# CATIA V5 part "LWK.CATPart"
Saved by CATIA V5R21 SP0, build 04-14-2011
Part number: LWK.SLDPRT
Bounding box of the stored display mesh (mm): x -1.362 to 1.338, y -0.976 to 1.024, z 2.1 to 2.7
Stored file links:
  C:\Users\user\Desktop\CATIA文件\0-最新文件\LWK\LWK.CATPart
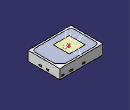
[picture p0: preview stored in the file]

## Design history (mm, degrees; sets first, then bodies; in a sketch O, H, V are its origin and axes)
AxisSystem1: origin (-0.0115, 0.0244, 2.7), X (0, 1, 0), Y (-1, 0, 0), Z (0, 0, 1)
Set1
  DatumSurface1 to DatumSurface42
  Line1: stored without definition
  Circle1: stored without definition
  Line2: stored without definition
  Circle2: stored without definition
  Line3: stored without definition
  Circle3: stored without definition
  Line4: stored without definition
  Circle4: stored without definition
  Line5: stored without definition
  Circle5: stored without definition
  Line6: stored without definition
  Circle6: stored without definition
  Line7: stored without definition
  Circle7: stored without definition
  Line8: stored without definition
  Line9: stored without definition
  Circle8: stored without definition
  Line10: stored without definition
  Line11: stored without definition
  Circle9: stored without definition
  Line12: stored without definition
  Line13: stored without definition
  Circle10: stored without definition
  Line14 to Line18: stored without definition
  Circle11: stored without definition
  Line19: stored without definition
  Circle12: stored without definition
  Line20: stored without definition
  Circle13: stored without definition
  Line21: stored without definition
  Circle14: stored without definition
  Line22: stored without definition
  Circle15: stored without definition
  Line23: stored without definition
  Circle16: stored without definition
  Line24: stored without definition
  Circle17: stored without definition
  Line25: stored without definition
  Circle18: stored without definition
  Line26: stored without definition
  Circle19: stored without definition
  Line27: stored without definition
  Circle20: stored without definition
  Line28 to Line30: stored without definition
  Circle21: stored without definition
  Line31: stored without definition
  Circle22: stored without definition
  Line32: stored without definition
  Circle23: stored without definition
  Line33: stored without definition
  Circle24: stored without definition
  Line34: stored without definition
  Line35: stored without definition
  Circle25: stored without definition
  Line36: stored without definition
  Circle26: stored without definition
  Line37: stored without definition
  Circle27: stored without definition
  Line38: stored without definition
  Circle28: stored without definition
  Line39: stored without definition
  Circle29: stored without definition
  Line40: stored without definition
  Circle30: stored without definition
  Line41: stored without definition
  Circle31: stored without definition
  Line42: stored without definition
  Circle32: stored without definition
  Line43: stored without definition
  Circle33: stored without definition
  Line44 to Line46: stored without definition
  Circle34: stored without definition
  Line47: stored without definition
  Circle35: stored without definition
  Line48: stored without definition
  Circle36: stored without definition
  Line49: stored without definition
  Circle37: stored without definition
  Line50: stored without definition
  Circle38: stored without definition
  Line51 to Line79: stored without definition
  DatumSurface43 to DatumSurface79
  Line80: stored without definition
  Circle39: stored without definition
  Line81: stored without definition
  Circle40: stored without definition
  Line82: stored without definition
  Circle41: stored without definition
  Line83: stored without definition
  Circle42: stored without definition
  Circle43: stored without definition
  Line84 to Line87: stored without definition
  Circle44: stored without definition
  Line88 to Line90: stored without definition
  Circle45: stored without definition
  Line91 to Line93: stored without definition
  Circle46: stored without definition
  Line94: stored without definition
  Line95: stored without definition
  Circle47: stored without definition
  Line96: stored without definition
  Circle48: stored without definition
  Line97: stored without definition
  Circle49: stored without definition
  Line98 to Line100: stored without definition
  Circle50: stored without definition
  Line101: stored without definition
  Circle51: stored without definition
  Line102: stored without definition
  Circle52: stored without definition
  Line103: stored without definition
  Circle53: stored without definition
  Line104: stored without definition
  Circle54: stored without definition
  Line105 to Line107: stored without definition
  Circle55: stored without definition
  Line108: stored without definition
  Circle56: stored without definition
  Line109 to Line112: stored without definition
  Circle57: stored without definition
  Line113: stored without definition
  Circle58: stored without definition
  Line114: stored without definition
  Circle59: stored without definition
  Line115 to Line117: stored without definition
  Circle60: stored without definition
  Line118: stored without definition
  Circle61: stored without definition
  Line119: stored without definition
  Circle62: stored without definition
  Line120: stored without definition
  Circle63: stored without definition
  Line121: stored without definition
  Circle64: stored without definition
  Line122 to Line124: stored without definition
  Circle65: stored without definition
  Line125: stored without definition
  Circle66: stored without definition
  Line126 to Line153: stored without definition
  DatumSurface80 to DatumSurface154
  DatumCurve1
  DatumCurve2
  Circle67: stored without definition
  Line154: stored without definition
  Circle68: stored without definition
  Line155: stored without definition
  Line156: stored without definition
  Circle69: stored without definition
  Line157: stored without definition
  Circle70: stored without definition
  Line158 to Line160: stored without definition
  Circle71: stored without definition
  Line161: stored without definition
  Circle72: stored without definition
  Line162 to Line164: stored without definition
  Circle73: stored without definition
  Line165: stored without definition
  Circle74: stored without definition
  Line166 to Line168: stored without definition
  Circle75: stored without definition
  Line169: stored without definition
  Circle76: stored without definition
  Line170: stored without definition
  Line171: stored without definition
  Circle77: stored without definition
  Line172: stored without definition
  Circle78: stored without definition
  Line173: stored without definition
  Circle79: stored without definition
  Line174 to Line176: stored without definition
  Circle80: stored without definition
  Line177: stored without definition
  Circle81: stored without definition
  Line178: stored without definition
  Circle82: stored without definition
  Line179: stored without definition
  Circle83: stored without definition
  Line180: stored without definition
  Circle84: stored without definition
  Line181 to Line183: stored without definition
  Circle85: stored without definition
  Line184: stored without definition
  Circle86: stored without definition
  Line185 to Line187: stored without definition
  Circle87: stored without definition
  Line188: stored without definition
  Line189: stored without definition
  Circle88: stored without definition
  Line190: stored without definition
  Line191: stored without definition
  Circle89: stored without definition
  Line192 to Line198: stored without definition
  Circle90: stored without definition
  Line199 to Line202: stored without definition
  Circle91: stored without definition
  Line203: stored without definition
  Line204: stored without definition
  Circle92: stored without definition
  Line205 to Line208: stored without definition
  Circle93: stored without definition
  Line209: stored without definition
  Line210: stored without definition
  Circle94: stored without definition
  Line211 to Line216: stored without definition
  Circle95: stored without definition
  Line217 to Line219: stored without definition
  Circle96: stored without definition
  Line220 to Line229: stored without definition
  Circle97: stored without definition
  Line230: stored without definition
  Circle98: stored without definition
  Line231: stored without definition
  Circle99: stored without definition
  Line232: stored without definition
  Circle100: stored without definition
  Line233: stored without definition
  Circle101: stored without definition
  Line234: stored without definition
  Circle102: stored without definition
  Line235: stored without definition
  Circle103: stored without definition
  Line236: stored without definition
  Circle104: stored without definition
  Line237 to Line245: stored without definition
  Circle105: stored without definition
  Line246: stored without definition
  Circle106: stored without definition
  Line247: stored without definition
  Circle107: stored without definition
  Line248: stored without definition
  Circle108: stored without definition
  Line249: stored without definition
  Circle109: stored without definition
  Line250: stored without definition
  Circle110: stored without definition
  Line251: stored without definition
  Circle111: stored without definition
  Line252: stored without definition
  Circle112: stored without definition
  Line253: stored without definition
  Circle113: stored without definition
  Line254: stored without definition
  Circle114: stored without definition
  Line255: stored without definition
  Circle115: stored without definition
  Line256: stored without definition
  Circle116: stored without definition
  Line257: stored without definition
  Circle117: stored without definition
  Line258 to Line260: stored without definition
  Circle118: stored without definition
  Line261: stored without definition
  Circle119: stored without definition
  Line262: stored without definition
  Circle120: stored without definition
  Line263: stored without definition
  Circle121: stored without definition
  Line264: stored without definition
  Circle122: stored without definition
  Line265: stored without definition
  Circle123: stored without definition
  Line266: stored without definition
  Circle124: stored without definition
  Line267: stored without definition
  Circle125: stored without definition
  Line268: stored without definition
  Circle126: stored without definition
  Line269: stored without definition
  Circle127: stored without definition
  Line270: stored without definition
  Circle128: stored without definition
  Line271 to Line273: stored without definition
  Circle129: stored without definition
  Line274: stored without definition
  Circle130: stored without definition
  Line275: stored without definition
  Circle131: stored without definition
  Line276: stored without definition
  Circle132: stored without definition
  Line277 to Line313: stored without definition
  DatumCurve3
  Line314: stored without definition
  DatumCurve4
  Line315: stored without definition
  DatumCurve5
  Line316: stored without definition
  DatumCurve6
  Line317: stored without definition
  DatumCurve7
  Line318 to Line323: stored without definition
  DatumCurve8
  Line324: stored without definition
  DatumCurve9
  Line325: stored without definition
  DatumCurve10
  Line326: stored without definition
  DatumCurve11
  Line327: stored without definition
  DatumCurve12
  Line328 to Line336: stored without definition
  Point1 "几何中心（测试原点）": type Between, FirstPoint vertex [face of DatumSurface148], SecondPoint vertex [face of DatumSurface147], Ratio 0.5
  Point2 "发光中心": type Between, FirstPoint vertex [face of DatumSurface154], SecondPoint vertex [face of DatumSurface154], Ratio 0.5
  Point3 "虚拟坐标": (-0.003, 0.208, -0.09), relative to Point1, in AxisSystem1
Body1 (main body)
